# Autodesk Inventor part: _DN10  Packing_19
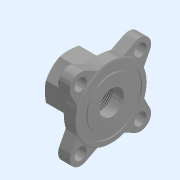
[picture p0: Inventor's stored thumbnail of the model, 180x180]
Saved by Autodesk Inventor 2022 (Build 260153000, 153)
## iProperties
Created: 2021-12
Part Number: _DN10  Packing_19
Material: Generico
Document SubType Name: Modeling
Designer: admin
Density: 1 g/cm^3
Appearance: Default
Author: admin
Revision Number: NONE
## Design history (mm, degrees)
feature "_DN10  Packing"
feature "Filettatura1" dims "d0" = 15, "d1" = 0
node "Solido1"
